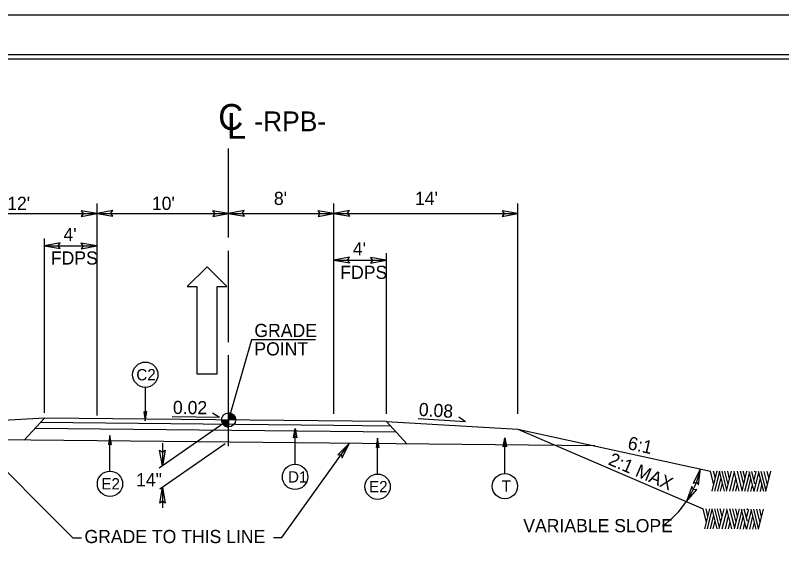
# Model space of a CAD drawing. Extents: x 573748 to 574632, y -54663 to -53209.
# Drawn here: x 574020.8 to 574108.2, y -54209.9 to -54148.7 of the extents above; entities that cross this region are included whole.
import ezdxf

# ---------------------------------------------------------------- set-up
doc = ezdxf.new("R2010")
doc.units = 0
for name, color, linetype in [('Prop Dimension', 7, 'Continuous'), ('Prop Dimension Text', 7, 'Continuous'), ('Prop Lane Arrow CELL', 7, 'Continuous'), ('Prop Terminator CELL', 7, 'Continuous'), ('Sheet Cutting Line CELL', 7, 'Continuous'), ('Sheet Plot Border Inside CELL', 7, 'Continuous'), ('Sheet Plot Border Outside CELL', 7, 'Continuous'), ('Sheet Typical CELL', 7, 'Continuous'), ('Typical Arrow Superelevation CELL', 7, 'Continuous'), ('Typical Grade Point Symbol CELL', 7, 'Continuous'), ('Typical Hinge Slope Arterial CELL', 7, 'Continuous'), ('Typical ID Circle CELL', 7, 'Continuous'), ('Typical Pavement Slope CELL', 7, 'Continuous'), ('Typical Slope Point Local CELL', 7, 'Continuous'), ('Typical Terminator CELL', 7, 'Continuous'), ('Typical Text Centerline CELL', 7, 'Continuous'), ('Typical Text General CELL', 7, 'Continuous'), ('Typical Text ID Circle CELL', 7, 'Continuous')]:
    doc.layers.add(name, color=color, linetype=linetype)

# ---------------------------------------------------------------- blocks, each defined once
blk = doc.blocks.new('CENTERLINE TEXT CL')
at = {"layer": 'Typical Text Centerline CELL'}
blk.add_text('C', height=1.64, dxfattribs=at).set_placement((-0.546, -0.261))
blk.add_text('L', height=1.641, rotation=359.9469, dxfattribs=at).set_placement((-0.001, -0.821))

msp = doc.modelspace()

# ---------------------------------------------------------------- linework, layer by layer
at = {"layer": 'Prop Dimension'}
for p, q in [((574045.148, -54173.999), (574045.148, -54163.829)), ((574030.148, -54194.26), (574030.148, -54170.114)), ((574057.148, -54194.064), (574057.148, -54170.114)), ((574078.148, -54194.064), (574078.148, -54170.114)), ((574012.148, -54171.244), (574030.148, -54171.244)), ((574030.148, -54171.244), (574045.148, -54171.244)), ((574045.148, -54171.244), (574057.148, -54171.244)), ((574057.148, -54171.244), (574078.148, -54171.244)), ((574024.148, -54193.961), (574024.148, -54174.109)), ((574024.148, -54174.938), (574030.133, -54174.938)), ((574045.148, -54185.899), (574045.148, -54175.51)), ((574057.148, -54176.568), (574063.133, -54176.568)), ((574063.148, -54194.064), (574063.148, -54175.767)), ((574045.148, -54197.762), (574045.148, -54187.384)), ((574044.59, -54195.163), (574037.218, -54200.287)), ((574044.743, -54197.51), (574037.313, -54202.673)), ((574037.607, -54197.413), (574037.607, -54200.017)), ((574037.607, -54202.47), (574037.607, -54204.805))]:
    msp.add_line(p, q, dxfattribs=at)
for points in [[(574055.079, -54185.665), (574047.771, -54185.665), (574045.148, -54194.775)], [(574028.372, -54208.238), (574027.417, -54208.238), (574016.193, -54197.01)], [(574050.28, -54208.194), (574051.231, -54208.194), (574058.912, -54197.451)]]:
    msp.add_lwpolyline(points, dxfattribs=at)
msp.add_arc((574088.147, -54197.851), 11.119, 305.72108, 346.94139, dxfattribs=at)
at = {"layer": 'Prop Lane Arrow CELL'}
for p, q in [((574042.724, -54177.318), (574040.444, -54179.562)), ((574044.933, -54179.562), (574042.724, -54177.318)), ((574040.444, -54179.562), (574041.513, -54179.562)), ((574041.513, -54179.562), (574041.513, -54189.537)), ((574043.864, -54189.537), (574043.864, -54179.562)), ((574043.864, -54179.562), (574044.933, -54179.562)), ((574041.513, -54189.537), (574043.864, -54189.537))]:
    msp.add_line(p, q, dxfattribs=at)
at = {"layer": 'Prop Terminator CELL'}
for points in [[(574028.352, -54171.577), (574030.148, -54171.244), (574028.334, -54170.947), (574028.568, -54171.264)], [(574031.945, -54170.911), (574030.148, -54171.244), (574031.963, -54171.541), (574031.728, -54171.224)], [(574043.352, -54171.577), (574045.148, -54171.244), (574043.334, -54170.947), (574043.568, -54171.264)], [(574046.945, -54170.911), (574045.148, -54171.244), (574046.963, -54171.541), (574046.728, -54171.224)], [(574055.352, -54171.577), (574057.148, -54171.244), (574055.334, -54170.947), (574055.568, -54171.264)], [(574058.945, -54170.911), (574057.148, -54171.244), (574058.963, -54171.541), (574058.728, -54171.224)], [(574076.352, -54171.577), (574078.148, -54171.244), (574076.334, -54170.947), (574076.568, -54171.264)], [(574025.945, -54174.605), (574024.148, -54174.938), (574025.963, -54175.235), (574025.728, -54174.918)], [(574028.337, -54175.271), (574030.133, -54174.938), (574028.318, -54174.641), (574028.553, -54174.959)], [(574058.945, -54176.235), (574057.148, -54176.568), (574058.963, -54176.865), (574058.728, -54176.548)], [(574061.337, -54176.901), (574063.133, -54176.568), (574061.318, -54176.271), (574061.553, -54176.588)], [(574058.117, -54199.096), (574058.912, -54197.451), (574057.599, -54198.738), (574057.993, -54198.737)], [(574037.917, -54198.216), (574037.607, -54200.017), (574037.287, -54198.206), (574037.607, -54198.436)], [(574098.737, -54202.174), (574098.979, -54200.363), (574098.133, -54201.996), (574098.507, -54201.872)], [(574037.297, -54204.27), (574037.607, -54202.47), (574037.927, -54204.28), (574037.607, -54204.05)], [(574097.992, -54202.384), (574097.349, -54204.094), (574098.54, -54202.694), (574098.148, -54202.73)]]:
    msp.add_lwpolyline(points, close=True, dxfattribs=at)
at = {"layer": 'Sheet Cutting Line CELL'}
msp.add_line((574280.971, -54148.659), (573944.171, -54148.659), dxfattribs=at)
at = {"layer": 'Sheet Plot Border Inside CELL'}
msp.add_lwpolyline([(574280.071, -54153.149), (573946.771, -54153.149), (573946.771, -54364.169), (574280.071, -54364.169)], close=True, dxfattribs=at)
at = {"layer": 'Sheet Plot Border Outside CELL'}
msp.add_lwpolyline([(574280.971, -54148.659), (573944.171, -54148.659), (573944.171, -54368.659), (574280.971, -54368.659)], close=True, dxfattribs=at)
at = {"layer": 'Sheet Typical CELL'}
msp.add_lwpolyline([(574277.571, -54153.659), (573977.571, -54153.659), (573977.571, -54363.659), (574277.571, -54363.659)], close=True, dxfattribs=at)
at = {"layer": 'Typical Arrow Superelevation CELL'}
for p, q in [((574044.1, -54194.487), (574043.312, -54194.022)), ((574044.1, -54194.487), (574038.706, -54194.438)), ((574072.157, -54194.985), (574066.773, -54194.65)), ((574072.157, -54194.985), (574071.394, -54194.479))]:
    msp.add_line(p, q, dxfattribs=at)
at = {"layer": 'Typical Grade Point Symbol CELL'}
for p, q in [((574045.148, -54194.775), (574045.148, -54193.97)), ((574044.342, -54194.775), (574045.148, -54194.775)), ((574045.146, -54195.581), (574045.148, -54194.775)), ((574045.148, -54194.775), (574045.146, -54195.581)), ((574045.954, -54194.775), (574045.148, -54194.775))]:
    msp.add_line(p, q, dxfattribs=at)
for points in [[(574045.155, -54193.97), (574045.155, -54193.97), (574045.155, -54194.775)], [(574045.171, -54193.97), (574045.171, -54194.775)], [(574045.188, -54193.971), (574045.188, -54194.775)], [(574045.204, -54193.971), (574045.204, -54194.775)], [(574045.22, -54193.973), (574045.22, -54194.775)], [(574045.236, -54193.975), (574045.236, -54194.775)], [(574045.252, -54193.977), (574045.252, -54194.775)], [(574045.268, -54193.979), (574045.268, -54194.775)], [(574045.284, -54193.98), (574045.284, -54194.775)], [(574045.3, -54193.984), (574045.3, -54194.775)], [(574045.316, -54193.988), (574045.316, -54194.775)], [(574045.333, -54193.991), (574045.333, -54194.775)], [(574045.349, -54193.995), (574045.349, -54194.775)], [(574045.365, -54194), (574045.365, -54194.775)], [(574045.381, -54194.004), (574045.381, -54194.775)], [(574045.397, -54194.009), (574045.397, -54194.775)], [(574045.413, -54194.014), (574045.413, -54194.775)], [(574045.429, -54194.02), (574045.429, -54194.775)], [(574045.445, -54194.027), (574045.445, -54194.775)], [(574045.461, -54194.034), (574045.461, -54194.775)], [(574045.478, -54194.041), (574045.478, -54194.775)], [(574045.494, -54194.048), (574045.494, -54194.775)], [(574045.51, -54194.055), (574045.51, -54194.775)], [(574045.526, -54194.064), (574045.526, -54194.775)], [(574045.542, -54194.073), (574045.542, -54194.775)], [(574045.558, -54194.082), (574045.558, -54194.775)], [(574044.346, -54194.775), (574044.346, -54194.863)], [(574044.362, -54194.775), (574044.362, -54194.958)], [(574044.378, -54194.775), (574044.378, -54195.015)], [(574044.394, -54194.775), (574044.394, -54195.064)], [(574044.41, -54194.775), (574044.41, -54195.101)], [(574044.427, -54194.775), (574044.427, -54195.135)], [(574044.443, -54194.775), (574044.443, -54195.165)], [(574044.459, -54194.775), (574044.459, -54195.194)], [(574044.475, -54194.775), (574044.475, -54195.219)], [(574044.491, -54194.775), (574044.491, -54195.243)], [(574044.507, -54194.775), (574044.507, -54195.264)], [(574044.523, -54194.775), (574044.523, -54195.284)], [(574044.539, -54194.775), (574044.539, -54195.303)], [(574044.556, -54194.775), (574044.556, -54195.321)], [(574044.572, -54194.775), (574044.572, -54195.339)], [(574044.588, -54194.775), (574044.588, -54195.355)], [(574044.604, -54194.775), (574044.604, -54195.37)], [(574044.62, -54194.775), (574044.62, -54195.384)], [(574044.636, -54194.775), (574044.636, -54195.398)], [(574044.652, -54194.775), (574044.652, -54195.411)], [(574044.668, -54194.775), (574044.668, -54195.423)], [(574044.684, -54194.775), (574044.684, -54195.434)], [(574044.701, -54194.775), (574044.701, -54195.445)], [(574044.717, -54194.775), (574044.717, -54195.456)], [(574044.733, -54194.775), (574044.733, -54195.466)], [(574044.749, -54194.775), (574044.749, -54195.475)], [(574044.765, -54194.775), (574044.765, -54195.484)], [(574044.781, -54194.775), (574044.781, -54195.493)], [(574044.797, -54194.775), (574044.797, -54195.5)], [(574044.813, -54194.775), (574044.813, -54195.508)], [(574044.829, -54194.775), (574044.829, -54195.515)], [(574044.846, -54194.775), (574044.846, -54195.522)], [(574044.862, -54194.775), (574044.862, -54195.529)], [(574044.878, -54194.775), (574044.878, -54195.534)], [(574044.894, -54194.775), (574044.894, -54195.54)], [(574044.91, -54194.775), (574044.91, -54195.545)], [(574044.926, -54194.775), (574044.926, -54195.549)], [(574044.942, -54194.775), (574044.942, -54195.554)], [(574044.958, -54194.775), (574044.958, -54195.558)], [(574044.974, -54194.775), (574044.974, -54195.561)], [(574044.991, -54194.775), (574044.991, -54195.565)], [(574045.007, -54194.775), (574045.007, -54195.568)], [(574045.023, -54194.775), (574045.023, -54195.57)], [(574045.039, -54194.775), (574045.039, -54195.574)], [(574045.055, -54194.775), (574045.055, -54195.575)], [(574045.071, -54194.775), (574045.071, -54195.577)], [(574045.087, -54194.775), (574045.087, -54195.579)], [(574045.103, -54194.775), (574045.103, -54195.579)], [(574045.12, -54194.775), (574045.12, -54195.581)], [(574045.136, -54194.775), (574045.136, -54195.581), (574045.136, -54195.581)], [(574045.574, -54194.091), (574045.574, -54194.775)], [(574045.59, -54194.102), (574045.59, -54194.775)], [(574045.606, -54194.113), (574045.606, -54194.775)], [(574045.623, -54194.125), (574045.623, -54194.775)], [(574045.639, -54194.136), (574045.639, -54194.775)], [(574045.655, -54194.149), (574045.655, -54194.775)], [(574045.671, -54194.163), (574045.671, -54194.775)], [(574045.687, -54194.177), (574045.687, -54194.775)], [(574045.703, -54194.192), (574045.703, -54194.775)], [(574045.719, -54194.208), (574045.719, -54194.775)], [(574045.735, -54194.224), (574045.735, -54194.775)], [(574045.751, -54194.242), (574045.751, -54194.775)], [(574045.768, -54194.261), (574045.768, -54194.775)], [(574045.784, -54194.281), (574045.784, -54194.775)], [(574045.8, -54194.303), (574045.8, -54194.775)], [(574045.816, -54194.326), (574045.816, -54194.775)], [(574045.832, -54194.351), (574045.832, -54194.775)], [(574045.848, -54194.378), (574045.848, -54194.775)], [(574045.864, -54194.406), (574045.864, -54194.775)], [(574045.88, -54194.44), (574045.88, -54194.775)], [(574045.896, -54194.478), (574045.896, -54194.775)], [(574045.913, -54194.523), (574045.913, -54194.775)], [(574045.929, -54194.578), (574045.929, -54194.775)], [(574045.945, -54194.661), (574045.945, -54194.775)]]:
    msp.add_lwpolyline(points, dxfattribs=at)
msp.add_circle((574045.147, -54194.775), 0.806, dxfattribs=at)
for start, end in [(359.99048, 89.99048), (179.99048, 269.99048)]:
    msp.add_arc((574045.147, -54194.775), 0.806, start, end, dxfattribs=at)
at = {"layer": 'Typical Hinge Slope Arterial CELL'}
for q in [(574100.099, -54200.607), (574099.249, -54204.911)]:
    msp.add_line((574078.148, -54195.832), q, dxfattribs=at)
at = {"layer": 'Typical ID Circle CELL'}
for p, q in [((574035.651, -54191.066), (574035.651, -54194.892)), ((574052.726, -54199.829), (574052.726, -54195.746)), ((574031.626, -54200.619), (574031.626, -54196.535)), ((574062.148, -54200.945), (574062.148, -54196.861)), ((574076.654, -54200.886), (574076.654, -54196.802))]:
    msp.add_line(p, q, dxfattribs=at)
for centre in [(574035.651, -54189.623), (574052.725, -54201.272), (574031.626, -54202.061), (574062.148, -54202.387), (574076.654, -54202.328)]:
    msp.add_circle(centre, 1.443, dxfattribs=at)
at = {"layer": 'Typical Pavement Slope CELL'}
for p, q in [((574024.148, -54194.558), (574012.148, -54195.255)), ((574021.852, -54197.068), (574024.148, -54194.558)), ((574063.148, -54194.961), (574024.148, -54194.558)), ((574063.148, -54194.961), (574078.148, -54195.832)), ((574065.488, -54197.519), (574063.148, -54194.961)), ((574064.252, -54196.168), (574023.065, -54195.742)), ((574057.148, -54195.428), (574023.669, -54195.082)), ((574063.637, -54195.495), (574057.148, -54195.428)), ((574086.921, -54197.741), (574004.631, -54196.89))]:
    msp.add_line(p, q, dxfattribs=at)
at = {"layer": 'Typical Slope Point Local CELL'}
for p, q in [((574100.481, -54202.157), (574100.099, -54200.607)), ((574100.3, -54202.888), (574100.863, -54200.592)), ((574100.654, -54201.471), (574100.442, -54200.607)), ((574100.603, -54202.888), (574101.151, -54200.674)), ((574101.702, -54202.888), (574101.135, -54200.607)), ((574101.702, -54201.67), (574101.442, -54200.607)), ((574102.119, -54202.135), (574101.737, -54200.607)), ((574101.934, -54202.888), (574102.497, -54200.607)), ((574102.284, -54201.478), (574102.072, -54200.607)), ((574102.3, -54202.888), (574102.84, -54200.711)), ((574103.379, -54202.888), (574102.812, -54200.607)), ((574103.714, -54202.822), (574103.166, -54200.607)), ((574103.887, -54202.113), (574103.517, -54200.607)), ((574103.698, -54202.888), (574104.261, -54200.607)), ((574104.048, -54201.449), (574103.843, -54200.607)), ((574104.036, -54202.888), (574104.572, -54200.718)), ((574105.076, -54202.925), (574104.505, -54200.637)), ((574105.158, -54202.069), (574104.804, -54200.637)), ((574105.072, -54201.604), (574105.312, -54200.637)), ((574105.084, -54202.925), (574105.623, -54200.755)), ((574105.158, -54200.747), (574105.135, -54200.637)), ((574105.202, -54200.711), (574105.174, -54200.607)), ((574106.166, -54202.925), (574105.595, -54200.637)), ((574106.442, -54202.851), (574105.895, -54200.637)), ((574106.607, -54202.194), (574106.221, -54200.637)), ((574106.426, -54202.925), (574106.989, -54200.629)), ((574106.777, -54201.508), (574106.564, -54200.637)), ((574100.938, -54202.888), (574101.316, -54201.331)), ((574101.969, -54202.748), (574101.702, -54201.67)), ((574102.647, -54202.888), (574103.013, -54201.404)), ((574104.343, -54202.925), (574104.706, -54201.441)), ((574105.095, -54201.478), (574105.072, -54201.39)), ((574105.434, -54202.925), (574105.796, -54201.441)), ((574101.257, -54202.888), (574101.477, -54201.988)), ((574102.993, -54202.888), (574103.182, -54202.098)), ((574104.698, -54202.925), (574104.883, -54202.157)), ((574105.788, -54202.925), (574105.973, -54202.157)), ((574099.631, -54206.461), (574099.249, -54204.911)), ((574099.449, -54207.192), (574100.012, -54204.896)), ((574099.804, -54205.775), (574099.591, -54204.911)), ((574099.753, -54207.192), (574100.3, -54204.978)), ((574100.851, -54207.192), (574100.284, -54204.911)), ((574100.851, -54205.974), (574100.591, -54204.911)), ((574101.268, -54206.439), (574100.886, -54204.911)), ((574101.083, -54207.192), (574101.646, -54204.911)), ((574101.434, -54205.782), (574101.221, -54204.911)), ((574101.449, -54207.192), (574101.989, -54205.015)), ((574102.528, -54207.192), (574101.961, -54204.911)), ((574102.863, -54207.126), (574102.316, -54204.911)), ((574103.036, -54206.417), (574102.666, -54204.911)), ((574102.847, -54207.192), (574103.41, -54204.911)), ((574103.197, -54205.753), (574102.993, -54204.911)), ((574103.186, -54207.192), (574103.721, -54205.022)), ((574104.225, -54207.229), (574103.654, -54204.941)), ((574104.308, -54206.373), (574103.953, -54204.941)), ((574104.221, -54205.908), (574104.461, -54204.941)), ((574104.233, -54207.229), (574104.772, -54205.059)), ((574104.308, -54205.052), (574104.284, -54204.941)), ((574104.351, -54205.015), (574104.323, -54204.911)), ((574105.316, -54207.229), (574104.745, -54204.941)), ((574105.591, -54207.155), (574105.044, -54204.941)), ((574105.757, -54206.498), (574105.371, -54204.941)), ((574105.575, -54207.229), (574106.138, -54204.933)), ((574105.926, -54205.812), (574105.713, -54204.941)), ((574100.087, -54207.192), (574100.465, -54205.635)), ((574100.406, -54207.192), (574100.627, -54206.292)), ((574101.119, -54207.052), (574100.851, -54205.974)), ((574101.796, -54207.192), (574102.162, -54205.709)), ((574103.493, -54207.229), (574103.855, -54205.745)), ((574104.245, -54205.782), (574104.221, -54205.694)), ((574104.583, -54207.229), (574104.946, -54205.745)), ((574102.142, -54207.192), (574102.331, -54206.402)), ((574103.847, -54207.229), (574104.032, -54206.461)), ((574104.938, -54207.229), (574105.123, -54206.461))]:
    msp.add_line(p, q, dxfattribs=at)
at = {"layer": 'Typical Terminator CELL'}
for points in [[(574035.469, -54193.837), (574035.651, -54194.892), (574035.838, -54193.832), (574035.651, -54193.966)], [(574052.544, -54196.8), (574052.726, -54195.746), (574052.913, -54196.806), (574052.726, -54196.671)], [(574031.808, -54197.59), (574031.626, -54196.535), (574031.438, -54197.596), (574031.626, -54197.461)], [(574062.329, -54197.916), (574062.148, -54196.861), (574061.96, -54197.922), (574062.148, -54197.787)], [(574076.473, -54197.857), (574076.654, -54196.802), (574076.842, -54197.862), (574076.654, -54197.728)]]:
    msp.add_lwpolyline(points, close=True, dxfattribs=at)

# ---------------------------------------------------------------- block references
at = {"layer": 'Prop Dimension', "xscale": 1.8000000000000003, "yscale": 1.8000000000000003}
msp.add_blockref('CENTERLINE TEXT CL', (574044.952, -54161.251), dxfattribs=at)

# ---------------------------------------------------------------- texts
at = {"layer": 'Prop Dimension'}
msp.add_text('GRADE TO THIS LINE', height=1.5, dxfattribs=at).set_placement((574028.716, -54208.818))
at = {"layer": 'Prop Dimension Text'}
for s, height, p in [('-RPB-', 2.25, (574048.079, -54161.868)), ("12'", 1.5, (574019.904, -54170.841)), ("10'", 1.5, (574036.404, -54170.841)), ("8'", 1.5, (574050.317, -54170.275)), ("14'", 1.5, (574066.404, -54170.275)), ("4'", 1.5, (574026.317, -54174.389)), ("4'", 1.5, (574059.317, -54176.019)), ('FDPS', 1.5, (574024.889, -54177.07)), ('FDPS', 1.5, (574057.889, -54178.7)), ('GRADE', 1.5, (574048.092, -54185.327)), ('POINT', 1.5, (574048.092, -54187.427)), ('14"', 1.5, (574034.606, -54202.341))]:
    msp.add_text(s, height=height, dxfattribs=at).set_placement(p)
for s, rotation, p in [('0.02', 359.47809, (574038.801, -54194.096)), ('0.08', 356.43884, (574066.805, -54194.309)), ('6:1', 347.72792, (574090.572, -54198.091)), ('2:1 MAX', 336.89371, (574088.339, -54199.827))]:
    msp.add_text(s, height=1.5, rotation=rotation, dxfattribs=at).set_placement(p)
at = {"layer": 'Typical Text General CELL'}
msp.add_text('VARIABLE SLOPE', height=1.5, dxfattribs=at).set_placement((574078.754, -54207.576))
at = {"layer": 'Typical Text ID Circle CELL'}
for s, height, p in [('C2', 1.2912, (574034.63, -54190.266)), ('D1', 1.2912, (574051.933, -54201.914)), ('E2', 1.2912, (574030.644, -54202.704)), ('E2', 1.2912, (574061.166, -54203.03)), ('T', 1.291, (574076.304, -54202.971))]:
    msp.add_text(s, height=height, dxfattribs=at).set_placement(p)

doc.saveas('drawing.dxf')
